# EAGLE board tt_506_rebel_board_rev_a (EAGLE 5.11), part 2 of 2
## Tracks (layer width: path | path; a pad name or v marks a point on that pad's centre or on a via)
+3.3V  (via drill 0.38 pad 0.64)
  Top 0.305: 105.09,55.88 104.46,55.88 98.11,49.53 v97.47,49.53 | v97.16,38.73 97.16,21.91 96.52,21.27 67.63,21.27 65.72,19.37 59.69,19.37 59.37,19.37 58.74,19.37 55.56,16.19 55.56,15.56 52.7,12.7 v51.44,12.7 | 78.42,67.7 78.42,66.99 78.11,66.67 75.88,66.67 75.75,66.54 U$1.5 73.21,66.54 73.03,66.36 73.03,66.04 73.17,65.89 U$1.4 | 78.42,67.7 C3.1 | 73.03,88.9 R76.1 62.13,90.7 62.23,90.81 C55.1 R77.1 | R44.1 72.92,89 73.03,88.9 | 78.42,67.7 79.13,67.7 79.38,67.94 79.38,68.9 79.69,69.22 80.11,69.22 C23.2 80.33,77.88 | v82.23,88.9 73.03,88.9 | v82.23,83.5 v82.23,86.36 | 82.23,77.88 v82.23,79.38 | v41.91,12.7 26.61,12.7 R37.1 24.83,11.93 R9.1 | 78.11,77.88 C139.+
  Top 0.406: QG1.4 75.61,77.99 C119.1 78.11,77.88 80.33,77.88 82.23,77.88 99.29,77.88 102.87,74.3 102.87,67.94 105.09,65.72 105.09,55.88 105.09,55.77 JS2.2
  Bottom 0.305: v41.91,12.7 v51.44,12.7 | v82.23,86.36 v82.23,88.9 | v82.23,79.38 v82.23,83.5 | v97.47,49.53 97.47,39.05 v97.16,38.73
  Bottom 0.406: JS2.2 108.15,55.77 109.86,57.15 R94.3
+5.0V
  Top 0.305: JS2.3 104.34,53.23 97.47,46.35 83.82,46.35 83.5,46.04 83.5,44.52 R30.2 83.31,41.59 R28.2
+8.0V  (via drill 0.38 pad 0.64, 0.38 pad 0.81)
  Top 0.305: 127.39,61.13 127.48,61.21 137.64,61.21 | 127.39,54.36 127.39,61.63 127.48,61.72 137.89,61.72 137.89,60.71 127.73,60.71 127.73,60.2 137.89,60.2 137.89,59.69 127.73,59.69 127.73,59.18 137.89,59.18 137.89,58.67 127.73,58.67 127.73,58.42 137.89,58.42 137.89,58.17 127.73,58.17 127.73,57.66 137.89,57.66 137.89,57.4 127.48,57.4 127.48,56.9 | v111.76,64.14 111.73,64.14 | R67.2 100.97,66.99 v103.82,64.14 103.82,57.47 97.16,50.8 v95.57,50.8 | v94.61,33.02 94.61,37.78 v95.57,38.73 | v87.95,33.02 72.39,33.02 70.17,30.8 70.17,28.57 v65.09,23.5 | v117.47,60.83 v117.47,50.48 | v115.89,47.62 115.89,42.86 116.2,42.55 115.99,42.55 R100.1 | v55.24,23.5 53.98,23.5 52.7,24.77 52.7,25.4 52.39,25.72 49.53,25.72 48.9,25.08 R75.1
  Top 0.406: 127.48,61.47 137.64,61.47 137.64,61.21 137.64,60.96 127.98,60.96 127.98,60.45 137.64,60.45 137.64,59.94 127.98,59.94 127.98,59.44 137.64,59.44 137.64,58.93 127.98,58.93 127.98,57.91 137.64,57.91 137.64,57.15 127.98,57.15 127.98,56.13 137.64,56.13 137.64,55.63 124.17,55.63 124.17,54.89 C114.1 124.24,56.83 124.17,56.9
  Top 0.61: 127.39,54.36 R38.1 | R60.2 111.88,67.16 112.24,66.8 112.72,66.8 Q7.2
  Top 0.813: v119.6,60.71 124.17,56.9 127.48,56.9 131.79,56.9 132.05,57.15 U1.4 | R60.2 111.09,67.09 111.09,65.6 111.73,64.96 111.73,64.14 v111.73,60.83
  Bottom 0.305: v103.82,64.14 v111.76,64.14 | v55.24,23.5 v65.09,23.5 | v95.57,38.73 v95.57,50.8 | v87.95,33.02 v94.61,33.02 | v117.47,50.48 v115.89,47.62
  Bottom 0.813: v111.73,60.83 v117.47,60.83 119.47,60.83 v119.6,60.71
  pour Top: 142.78,54.61 119.35,54.61 119.35,75.82 142.78,75.82
+12V  (via drill 0.38 pad 0.61, 0.38 pad 0.64, 0.7 pad 1.02, 0.8 pad 1.02)
  Top 0.305: v28.8,38.99 28.8,40.71 L2.2 | 28.86,28.45 v28.8,28.51 | 123.83,49.12 123.19,48.9 123.38,49.09 123.51,49.09 123.79,48.8 | 89.64,39.9 v89.22,40.01 89.32,39.9 R47.2
  Top 0.406: J3.3 105.96,66.45 104.14,68.26 104.14,74.93 97.79,81.28 67.63,81.28 62.87,76.52 62.87,75.25 59.37,71.75 57.61,71.75 R32.1 | R56.1 139.07,26.99 v140.02,27.94
  Top 0.61: 28.86,28.45 28.77,28.45 26.99,26.67 26.99,16.83 26.83,16.67 | R59.2 131.09,49.37 131.03,49.31
  Top 0.813: J3.2 107.6,68.97 107.6,68.77 107.59,68.76 J3.3 107.59,63.39 109.22,61.75 109.22,51.44 109.54,51.12 109.54,48.9 | C117.1 136.79,50.74 136.84,50.8
  Top 1.016: v89.22,40.01 89.22,32.07 88.58,31.43 73.66,31.43 72.07,29.84 72.07,27.62 v67.94,23.5 | 107.47,45.72 JS2.6 | 107.47,45.72 109.54,45.72 109.54,48.9 109.73,49.09 123.51,49.09 130.81,49.09 131.03,49.31 132.84,51.12 134.31,51.12 U1.3 135.28,51.09 135.57,50.8 136.84,50.8 | 136.84,50.8 141.29,50.8 142.24,49.85 v142.24,27.94 142.24,21.27 U$174.P$1 137.79,16.83 C147.+ | v50.8,18.1 38.1,18.1 36.51,16.51 26.99,16.51 26.83,16.67 24.77,18.73 X3.1 | 136.84,50.8 136.84,52.62 C141.+ | v89.22,45.09 104.78,45.09 105.41,45.72 107.47,45.72
  Bottom 0.305: v142.24,27.94 v140.02,27.94
  Bottom 0.381: v28.8,28.51 v28.8,38.99
  Bottom 1.016: v50.8,18.1 53.66,18.1 55.88,20.32 64.77,20.32 v67.94,23.5 | v89.22,40.01 v89.22,45.09
BAND_DETECT  (via drill 0.38 pad 0.64)
  Top 0.305: JS5.16 61.84,69.14 66.67,73.98 66.67,77.47 68.26,79.06 v68.26,79.38 | v68.26,83.5 68.26,85.09 v69.53,86.36 | v69.53,90.17 69.85,90.49 R44.2 71.12,90.59 71.12,92.71 69.85,93.98 X4.1
  Bottom 0.305: v68.26,79.38 v68.26,83.5 | v69.53,86.36 v69.53,90.17
BAND_END_FLASH_LED
  Top 0.406: JS7.10 102.55,30.37 R85.2
BATTERY
  Top 0.305: JS7.5 107.63,35.5 107.63,36.2 107,36.83 98.74,36.83 | 98.74,36.51 R47.1 98.74,38.42
  Top 0.406: 98.74,36.51 R80.1 98.74,36.83
CODE_READ  (via drill 0.38 pad 0.64)
  Top 0.305: v108.58,43.18 U$184.P$1 C99.1
  Bottom 0.305: JS7.2 105.03,42.49 105.73,43.18 v108.58,43.18
CW_SPEED  (via drill 0.38 pad 0.64)
  Top 0.305: JS7.4 105.03,38.68 105.73,39.37 111.12,39.37 111.76,40.01 v111.76,41.91 | v111.76,44.45 v111.76,46.99 | v111.76,51.44 111.76,53.34 R94.2
  Bottom 0.305: v111.76,41.91 v111.76,44.45 | v111.76,46.99 v111.76,51.44
ENC_A  (via drill 0.38 pad 0.64)
  Top 0.305: v67.94,46.99 68.58,46.35 75.25,46.35 76.8,44.81 C50.1 76.83,44.26 R35.1
  Bottom 0.305: JS6.15 59.28,46.58 59.69,46.99 v67.94,46.99
ENC_B  (via drill 0.38 pad 0.64)
  Top 0.305: 78.17,41.66 R34.1 78.18,41.59 | v67.63,41.59 78.18,41.59 | 78.18,41.59 78.18,40.15 C49.1
  Bottom 0.305: JS6.13 59.28,42.29 59.91,41.66 67.56,41.66 v67.63,41.59
FSYNC  (via drill 0.38 pad 0.64)
  Top 0.305: U$1.15 67.29,67.19 66.96,66.86 v66.96,53.53
  Bottom 0.305: v66.96,53.53 60.62,53.53 JS5.3
GND  (via drill 0.38 pad 0.61, 0.38 pad 0.64, 3.2 pad 6.45)  (2 unrouted)
  Top 0.305: R8.1 17.79,37.05 v17.49,37.08 | Q6.3 20.69,42.56 v20.8,42.67 | R6.1 26.21,38.94 v26.38,39.12 | C12.2 27.35,38.05 v27.4,38.67 | C2.2 v21.3,29.72 | R13.1 26.16,35.28 v26.13,35.31 | U$1.12 69.21,69.11 v69.5,68.77 | U$1.7 72.7,67.84 v72.68,67.82 | U$1.18 69.46,65.24 v69.5,65.6 | v103.82,15.24 103.8,15.26 | U$34.2 v99.69,65.72 | U$57.2 v95.88,65.72 v95.89,65.72 | v96.84,70.17 R68.1 | R1.1 46.89,13.23 46.99,13.34 | 46.99,13.34 R2.1 | 46.99,14.92 R36.1 | 46.99,13.34 46.99,14.92 | R54.1 R53.1 | R54.1 96.94,14.19 96.84,14.29 97.05,14.29 R54.1 | R55.1 R54.1 | R55.1 95.03,14.19 94.93,14.29 95.15,14.29 R55.1 | R55.1 93.77,14.19 v93.66,14.29 | v76.83,70.8 76.8,70.77 | C3.2 78.42,69.53 | C36.2 v80.64,65.09 | C55.2 v65.09,90.81 | R78.1 24.34,35.46 v24.77,35.88 | R14.1 27.09,35.77 v26.35,36.2 | R81.2 v98.74,30.48 | R82.1 v100.33,27.94 | R3.2 v80.64,63.18 | 11.82,53.26 v11.75,53.34 | C13.2 19.17,46.23 v19.37,46.04 | R52.1 71.86,72.45 v71.41,72.9 | U$199.2 65.87,84.94 v66.04,84.77 | R63.2 62.21,86.7 v62.23,86.68 | R4.1 68.29,59.4 v68.26,59.37 | C4.2 70.01,59.53 v69.85,59.37 | C5.2 71.85,59.47 v71.75,59.37 | C17.2 73.75,59.47 v73.66,59.37 | R5.1 75.66,59.47 v75.56,59.05 | C18.2 77.22,58.48 v77.15,58.42 | C7.2 77.22,56.9 v77.15,56.83 | C10.2 89.66,65.28 v89.53,65.41 | C16.2 87.82,65.22 v87.63,65.41 | C8.2 85.12,65.37 v85.09,65.41 | C9.2 82.45,65.31 v82.55,65.41 | R23.2 26.23,3.94 v26.35,3.49 | U$204.2 107.8,22.71 v107.95,22.86 | v22.54,6.99 C130.2 | v119.06,20.64 119.11,20.59 | C49.2 75.03,40.1 v74.93,40.01 | C50.2 75.1,44.3 v73.66,44.13 | C131.2 v23.18,12.7 | R91.1 127.85,29.43 v127.95,29.53 | R74.2 123.41,29.95 v123.19,30.16 | R96.2 117.58,31.65 v117.47,31.75
  Top 0.305: R97.2 v117.47,33.34 | C93.- v117.47,38.73 | v115.89,32.07 R65.2 | 43.5,69.26 C74.2 | U$41.3 47.31,65.31 47.31,66.67 47.94,67.31 v48.26,67.31 | R29.1 54.29,65.14 | C75.2 47.99,63.18 | U$91.2 48.37,61.28 | L13.2 45.4,57.54 | C87.2 36.65,38.1 | 34.92,33.37 U$40.3 | C90.2 30.8,32.75 | C91.2 31.75,22.33 v31.75,23.5 | C78.2 39.37,25.08 v39.37,23.5 | 39.28,31.43 C137.- | C66.2 | D19.A 53.17,47.8 v53.02,47.94 53.17,48.09 D10.A | C82.2 46.78,47.1 v46.67,46.99 | C81.2 46.6,48.83 v46.67,48.9 | D11.A 39.86,48.09 v40.01,47.94 39.86,47.8 D18.A | C83.2 56.76,28.82 v56.83,28.89 | v32.7,37.15 C135.- | L16.2 52.31,30.08 v52.39,30.16 | D9.A 56.03,26.52 v56.2,26.35 56.03,26.18 D20.A | 46.99,14.92 47.94,14.92 v48.26,15.24
  Top 0.406: QG1.2 67.92,72.89 v67.91,72.9 | QG1.2 71.4,72.89 v71.41,72.9 | QG1.2 v69.51,74.48 v69.5,74.49 | 75.72,74.93 v75.85,74.8 | 124.17,53.06 124.01,52.9 122.84,52.9 122.21,52.26 121.38,52.26 | 103.8,15.26 R17.2 | C63.2 28.55,72.68 v29.21,72.71 | C62.2 28.41,71.28 v29.21,71.44 | C67.2 28.54,69.89 v29.21,69.85 | v26.04,55.56 25.87,55.73 | v27.3,55.56 27.27,55.6 | v28.57,55.56 28.66,55.79 | R10.1 33.11,53.25 v32.7,53.34 | 9.89,61.55 v9.84,61.59 | 120.33,5.97 U$176.2 | C132.2 12.8,15.77 v12.7,15.88 | C150.- v25.08,25.4 | 1.54,61.55 v1.59,61.59 | C136.- 137.07,28.49 v137.16,28.57 | C107.2 132.53,26.8 v132.4,26.67 | C51.2 67.63,74.81 v67.63,73.66
  Top 0.61: JS2.5 JS2.4 | C111.2 v116.81,76.2 | v121.38,50.55 121.38,52.26 | v124.17,51.88 124.17,53.06 C114.2 | C110.2 113.82,65.47 v113.76,65.53 | C119.2 75.72,74.93 | C65.2 39.76,76.27 v39.69,76.2 | C64.2 39.82,74.43 v39.69,74.3 | 25.87,55.73 C71.2 | 27.27,55.6 C72.2 | 28.66,55.79 C70.2 | R39.2 v125.74,52.38 v125.73,52.39 | 76.8,70.77 C1.2 | 78.42,69.53 v78.42,70.8 | v24.13,94.61 D12.A | C129.2 16.51,46.51 v15.97,45.97 | 11.82,53.26 C6.2 | C44.2 v15.56,78.11 | C37.2 v15.56,80.33 | C42.2 v14.61,62.87 | C123.2 v16.83,62.87 | C133.2 v15.88,64.45 | C33.2 v1.27,72.07 C34.2 | C48.2 v4.76,74.3 | C45.2 9.89,61.55 | v120.33,4.45 120.33,5.97 | v118.43,4.76 C120.2 | C149.- v31.43,53.66 | v113.67,61.91 113.67,63.5 | C142.- v113.98,77.79 | v78.11,73.03 C139.- | 119.11,20.59 C94.2 | LM358.4 124.61,21.12 v124.46,20.95 | C152.- v117.47,22.54 | C54.2 21.73,76.69 v21.59,76.83 | D5.C v18.41,80.64 | C43.2 1.54,61.55 | C29.2 v6.67,68.9 | 21.27,65.09 C39.2 | 21.27,65.09 v22.54,65.09 | v22.54,62.55 C122.2 21,64.82 21.27,65.09 | C25.- 28.8,50.4 v28.89,50.48 | C146.- 138.98,22.45 v138.11,21.59 | R45.2 119.18,19.16 v119.06,19.05 | C117.2 139.51,49.4 v139.7,49.21 | C100.2 v140.65,46.98 v140.65,46.99 | C109.2 139.63,47.06 v139.7,46.99 | LM386M-1.4 136.58,45.35 v136.53,45.4 | LM386M-1.2 136.58,42.81 v136.53,42.86 | C102.- 129.63,36.6 v129.54,36.51 | R51.1 133.76,47.4 v133.99,47.62 | C126.- v124.78,41.91 | v29.84,91.12 C128.2 | C56.2 30.8,85.22 v30.8,86.68 | v28.89,86.68 28.89,85.22 C57.2 28.94,85.09 27.03,85.09 | C58.2 27.03,85.09 | 27.03,85.09 v25.72,85.09 | C138.- 53.74,68.58 v55.24,68.58 | v43.5,67.94 43.5,69.26 | 54.29,65.14 v54.29,63.82 | 47.99,63.18 v49.21,63.18 | 48.37,61.28 v49.85,61.28
  Top 0.61: 45.4,57.54 v45.4,59.05 | 36.65,38.1 v38.1,38.1 | v34.92,31.43 34.92,33.37 | C125.2 v32.07,33.97 | 30.8,32.75 v30.8,33.97 | v31.11,24.45 C21.2 | v37.47,31.43 39.28,31.43 | v37.15,81.28 C66.2 | L1.1 49.44,24.22 v49.21,24.13 | R84.1 v116.84,20.64 | C151.- v119.38,12.7 | D6.A 121.5,9.63 v121.6,9.53
  Top 0.813: J4.2 142.78,84.23 v142.88,84.14
  Top 1.016: C141.- v141.6,52.7 | v137.79,9.53 C147.-
  Bottom 0.305: JS2.4 107.58,50.67 | v26.38,39.12 26.64,39.12 v27.4,38.67 | v78.42,70.8 v76.83,70.8 | MNT6.MNT 140.57,91.58 J1.1 130.67,91.44 120.97,91.44 119.7,92.71 | MNT7.MNT 140.97,6.57 140.97,6.67 134.46,10.32 U$162.5 U$162.4 124.83,13.63 U$162.1 | 93.66,13.97 v93.66,14.29 89.53,10.16 MNT2.MNT | 93.77,14.19 93.98,14.4 | 111.44,92.71 109.54,90.81 109.54,84.77 112.39,81.92 112.39,79.38 v113.98,77.79
  other vias: 11.4,27.81 11.58,32.51 3.52,21.34 7.08,45.97 5.3,38.1 5.3,36.07 3.52,37.08 5.05,45.97 5.3,34.04 5.3,32 5.3,29.97 5.3,27.94 7.33,27.94 9.37,27.94 3.52,35.05 3.52,33.02 3.52,30.99 3.52,28.96 3.52,26.92 15.53,27.75 13.43,27.75 5.56,21.34 7.59,21.34 9.62,21.34 11.65,21.34 13.43,21.34 13.43,23.37 3.52,23.37 3.52,25.15 15.34,21.34 17.24,21.34 19.15,21.34 21.05,21.34 22.96,21.34 24.86,21.34 24.86,23.24 22.96,23.24 21.05,23.24 19.15,23.24 17.24,23.24 15.34,23.24 5.49,23.24 7.72,23.24 9.62,23.24 11.53,23.24 15.53,25.53 13.3,25.53 11.4,25.53 9.18,25.53 7.27,25.53 5.37,25.53 7.27,33.78 7.27,31.88 7.27,29.97 7.27,35.69 15.84,29.97 15.84,31.88 15.84,33.78 15.84,35.69 15.84,37.59 15.84,39.81 7.27,37.59 7.27,39.81 9.18,36.96 13.94,36.96 11.4,36.96 9.49,39.81 13.62,39.81 15.84,42.04 7.27,42.04 7.27,43.94 15.84,43.94 9.49,42.04 13.94,42.04 13.94,43.94 9.49,43.94 11.72,42.99 11.72,40.77 5.08,43.81 5.08,42.23
  pour Top: 16.73,46.67 3.78,46.67 3.78,38.35 2.51,38.35 2.51,20.32 25.94,20.32 25.94,23.94 16.61,23.94 16.61,28.7
  pour Bottom: 0.22,95.5 0.29,0.38 59.05,0.32 59.05,18.1 85.72,18.1 85.72,0.32 87.95,0.32 98.04,0.38 144.56,0.38 144.49,95.5
MEDIUM_A8  (via drill 0.38 pad 0.64)
  Top 0.305: R71.1 97.79,63.18 98.42,62.55 101.92,62.55 102.55,61.91 v102.55,57.78
  Bottom 0.305: v102.55,57.78 102.55,35.88 102.87,35.56 104.92,35.56 JS7.6
MP_A  (via drill 0.38 pad 0.64)
  Top 0.305: v90.49,24.13 v90.49,38.73 | v90.49,17.46 90.49,16.83 91.76,15.56 100.01,15.56 100.65,14.92 100.65,10.79 U$168.P$2 | v67.94,55.56 72.39,55.56 74.3,53.66 89.53,53.66 90.49,52.7 v90.49,49.85
  Bottom 0.305: JS5.8 63.04,57.29 64.77,55.56 v67.94,55.56 | v90.49,38.73 v90.49,49.85 | v90.49,17.46 v90.49,24.13
MP_B  (via drill 0.38 pad 0.64)
  Top 0.305: v92.08,24.13 v92.08,38.73 | v92.08,17.46 92.08,17.14 92.71,16.51 100.33,16.51 101.6,15.24 101.6,7.62 100.97,6.99 U$168.P$4 | v69.22,56.52 72.71,56.52 74.61,54.61 90.81,54.61 92.08,53.34 v92.08,49.85
  Bottom 0.305: JS5.12 63.36,62.37 63.82,61.91 63.82,57.78 65.09,56.52 v69.22,56.52 | v92.08,38.73 v92.08,49.85 | v92.08,17.46 v92.08,24.13
MP_C  (via drill 0.38 pad 0.64)
  Top 0.305: v93.66,24.13 v93.66,38.73 | v93.66,17.46 100.65,17.46 102.55,15.56 102.55,5.4 101.6,4.45 U$168.P$6 | v67.94,57.47 73.03,57.47 74.93,55.56 92.08,55.56 93.66,53.98 v93.66,50.8
  Bottom 0.305: JS5.14 63.36,64.91 64.77,63.5 64.77,58.1 65.41,57.47 v67.94,57.47 | v93.66,38.73 v93.66,50.8 | v93.66,17.46 v93.66,24.13
N$1
  Top 0.61: 16.83,86.36 16.83,83.6 X1.1 19.75,83.44 21.27,81.92 21.27,80.2 L4.2 | 16.83,86.36 8.26,86.36 7.94,86.68 6.15,86.68 X11.2 | 16.83,86.36 23.18,86.36 24.45,87.63 C127.1
N$2  (via drill 0.38 pad 0.64)
  Top 0.305: JS5.1 60.69,51.05 63.12,51.05 v63.18,51.12 | U$1.14 68.19,67.82 66.83,67.82 66.01,66.99 66.01,53.02 66.99,52.04 v66.99,51.12
  Bottom 0.305: v63.18,51.12 v66.99,51.12
N$3
  Top 0.305: JS5.5 59.37,54.82 59.37,55.88 59.63,56.13 63.98,56.13 65.25,57.4 65.25,67.31 66.43,68.49 U$1.13
N$4
  Top 0.305: U$1.11 68.17,69.72 66.58,69.72 64.48,67.63 64.48,59.69 63.47,58.67 59.63,58.67 59.37,58.42 59.37,57.36 JS5.7
N$5
  Top 0.305: JS5.9 59.3,60.89 59.37,60.96 63.18,60.96 63.82,61.59 63.82,67.94 66.36,70.48 69.22,70.48 70.58,69.11 U$1.9
N$6
  Top 0.305: U$1.1 75.71,63.97 76.83,65.09 C36.1 R3.1
N$7
  Top 0.305: L15.2 80.39,58.68 C18.1 C7.1 82.2,56.9 L18.1
N$8
  Top 0.305: U$1.19 70.96,64.61 71.75,63.82 71.75,62.48 C5.1 73.63,62.38 C17.1 73.68,62.26 73.66,62.23 75.56,62.23 | 75.56,62.23 75.62,62.23 R5.2 75.6,62.19 75.56,62.23 | 75.56,62.23 75.56,61.91 77.15,61.91 77.47,61.59 77.47,60.61 L15.1
N$9
  Top 0.305: U$1.20 68.22,62.52 R4.2 C4.1
N$10
  Top 0.305: U$1.6 75.13,67.19 75.56,67.63 76.7,67.63 C1.1
N$11
  Top 0.305: L18.2 82.55,62.17 | 82.55,62.17 C9.1 | 82.55,62.17 82.64,62.27 C8.1 85.12,60.07 L17.1
N$12
  Top 0.305: U$160.3 25.28,30.23 24.61,30.23 23.82,31.01 R12.1 18.3,31.01 L14.2 18.26,32.91 U$159.3 18.62,35.56 C20.1
N$13  (via drill 0.38 pad 0.64)
  Top 0.305: v86.04,56.52 87.95,58.42 87.95,59.85 L17.2 C16.1 C10.1 | C11.2 46.67,51.36 47.62,50.48 v53.98,50.48 | v58.1,44.13 56.2,46.04 v56.2,46.99
  Top 0.406: v86.04,50.8 68.9,50.8 66.67,48.58 66.67,47.31 | 66.67,47.31 | 66.67,47.31 | v66.67,44.13 66.67,47.31
  Bottom 0.305: v58.1,44.13 v66.67,44.13 | v53.98,50.48 54.29,50.16 54.29,47.62 54.93,46.99 v56.2,46.99
  Bottom 0.406: v86.04,50.8 v86.04,56.52
N$14
  Top 0.305: 20.49,36.83 20.49,35.74 C20.2 | 20.49,36.83 R8.2 | 20.49,36.83 20.32,37 20.32,37.78 20,38.1 U$158.1 19.86,39.05 18.1,39.05 R86.1
N$15
  Top 0.305: U$159.2 22.61,34.22 22.86,33.97 R78.2
N$16
  Top 0.305: 24.4,32.36 U$160.2 24.33,32.43 | U$159.1 24.22,32.32 24.33,32.43 | 24.33,32.43 24.33,34.04 R13.2
N$17  (via drill 0.38 pad 0.64)
  Top 0.305: 27.62,32.34 U$160.1 | R40.1 27.62,32.34 | 27.62,32.34 27.62,33.97 27.94,33.97 R14.2 28.65,34.08 29.18,34.61 29.18,37.75 30.16,38.73 30.16,41.27 U$185.P$1 33.02,44.13 37.47,44.13 38.42,45.09 38.42,53.66 39.05,54.29 42.86,54.29 43.81,55.24 43.81,55.88 | C118.1 43.5,63.89 43.5,63.18 43.81,62.87 v43.81,60.64 | 43.81,55.88 v43.81,58.1 | C11.1 44.9,55.75 44.77,55.88 43.81,55.88
  Bottom 0.305: v43.81,58.1 v43.81,60.64
N$18
  Top 0.305: 23.33,39.03 R6.2 23.39,38.91 U$158.2 21.91,38.1 22.17,37.84 R22.2
N$19
  Top 0.305: R22.1 25.46,37.33 C12.1
N$20  (1 unrouted)
  Top 0.305: R15.1 20.16,27.91 C2.1
  Top 0.406: L14.1 18.41,28.26 18.41,27.94 18.44,27.91 18.44,26.33 19.05,25.4 20.39,25.4 20.16,26.12 20.16,27.91
N$21
  Top 0.305: U$158.3 21.1,41.1 21.91,41.91 21.91,43.18 | 21.91,43.18 21.59,43.18 20.4,44.37 Q6.1 | 21.91,43.18 23.62,43.18 C15.2 25.18,43.1 D1.C
N$22
  Top 0.381: D1.A D2.C
N$23
  Top 0.305: U$131.1 23.43,48.96 23.81,48.58 23.81,46.67 24.13,46.35 25.19,46.35 R20.1 25.21,44.96 25.4,44.77 25.72,44.77 25.72,45.09 25.46,45.09 D2.A
  Top 0.381: 23.78,44.89 C15.1 25.18,44.8 D2.A
N$24
  Top 0.305: 25.11,49.53 25.4,49.53 25.21,49.34 R20.2 25.3,47.94 26.04,47.94 26.35,47.62 27.07,47.62 C25.+ | 25.11,49.53 25.08,49.53 | 25.11,49.53 R33.1
N$25  (via drill 0.38 pad 0.64)
  Top 0.305: R50.2 140.59,38.48 140.97,38.1 140.97,22.54 135.25,16.83 v132.72,16.83 | C32.2 v129.54,16.83
  Bottom 0.305: v129.54,16.83 v132.72,16.83
N$26  (via drill 0.38 pad 0.61)
  Top 0.305: v22.19,44.32 22.19,46.32 22.54,46.67 22.54,47.38 U$131.3 22.19,47.16 C13.1
  Top 0.381: v23.46,40.83 L2.1
  Bottom 0.305: v22.19,44.32 22.19,44.16 22.54,43.81 22.54,41.75 v23.46,40.83
N$27
  Top 0.305: Q6.2 18.16,44.42 | U$131.2 21.42,49.54 C19.1 19.68,49.21 19.68,48.58 19.37,48.26 18.1,48.26 17.78,47.94 17.78,46.04 18.5,45.32 Q6.2 | R86.2 18.1,43.18 18.41,43.5 18.41,44.68 Q6.2
N$28
  Top 0.61: U$37.CLS 6.94,53.02 C46.1
N$29  (via drill 0.38 pad 0.64)
  Top 0.305: v70.8,23.18 78.42,23.18 79.69,24.45 v79.69,28.26 | v79.69,42.86 79.69,44.13 | 79.69,44.13 79.75,44.13 R35.2 | R30.1 79.88,44.32 79.69,44.13
  Bottom 0.305: X2.1 69.82,22.19 v70.8,23.18 | v79.69,28.26 v79.69,42.86
N$30
  Top 0.305: R21.2 33.04,51.75 33.02,51.75 32.7,52.07 27.3,52.07 26.99,52.39 26.99,53.66 C149.+ 18.41,53.66 18.38,53.62 18.1,53.34 17.78,53.02 16.59,53.02 R19.1 14.93,53.15 C6.1
N$31
  Top 0.305: RD16HHF1.1 14.18,49.95 | R19.2 16.51,51.4 C129.1 16.93,50.06 17.46,49.53 C19.2
  Top 0.406: C129.1 14.17,50.06 RD16HHF1.1
N$32
  Top 0.305: R21.3 37.15,46.62 37.15,53.98 37.7,54.53 R18.2
N$33
  Top 0.305: R10.2 35.88,53.23
  Top 0.406: R21.1 31.89,45.86 35.88,49.85 35.86,49.87 R10.2
N$34
  Top 0.406: R81.1 R80.2
N$35
  Top 0.61: U$37.GRS U$37.CLF
N$36
  Top 0.61: X6.2 6.17,57.02 8.89,54.29 8.89,53.7 C46.2
N$37
  Top 0.406: C45.1 6.54,61.35 TOROID2.P$1 4.89,61.35 C43.1 3.63,59.92 X6.1
  Top 0.61: C30.1 C24.1 1.86,65.22 TOROID2.P$1
N$38
  Top 0.406: C24.2 C30.2 | C30.2 3.86,70.44 3.81,70.48 3.81,70.22 C30.2 | C30.2 4.13,70.17 4.76,70.8 4.76,72.03 C34.1
  Top 0.61: C121.1 C47.1 7.26,80.64 TOROID1.P$1 9.53,78.38 6.67,75.52 C29.1 4.81,72.44 C34.1 | C24.2 5.4,67.94 5.71,67.63 TOROID2.P$2
N$39
  Top 0.61: C48.1 3.44,75.93 3.49,75.88 3.17,75.88 C48.1 | X11.1 1.66,85.17 1.27,84.77 1.27,82.82 | 1.27,82.82 C121.2 | 1.27,80.69 1.27,82.82 | 1.27,80.69 C47.2 | 1.27,78.42 1.27,80.69 | 1.27,78.42 4.25,78.42 TOROID1.P$2 | 1.27,78.42 C33.1 C48.1
N$40
  Top 0.61: TOROID4.P$1 17.66,55.2 C41.1 C124.1 12.11,55.2 11.75,55.56 11.75,57.47 | C123.1 C42.1 14.52,59.24 L3.1 12.25,59.24 12.25,58.1 11.75,57.47 | X6.3 8.88,57.47 11.75,57.47
N$41
  Top 0.61: C124.2 C41.2 16.88,57.2 17.14,57.47 18.73,57.47 | 13.09,66.99 TOROID3.P$1 | 13.09,66.99 13.09,68.97 14.92,70.8 14.92,73.98 14.61,74.3 C40.1 C38.1 | 18.73,57.47 21.48,57.47 TOROID4.P$2 | 18.73,57.47 19,57.74 C122.1 C39.1 19,66.09 18.1,66.99 13.09,66.99
N$42
  Top 0.61: X11.3 7.58,84.77 11.43,84.77 12.06,84.14 12.06,80.33 C37.1 | C37.1 12.06,80.38 | C37.1 C44.1 12.02,77.83 12.06,77.79 11.75,77.79 11.75,76.25 C38.2 C40.2 11.7,72.44 12.06,72.07 12.91,72.07 TOROID3.P$2
N$43
  Top 0.406: R38.2 127.44,52.7 R39.1 127.46,51.09 U1.1
N$44
  Top 0.305: D4.C 118.01,35.14 R65.1 115.89,36.73 R64.2
N$45  (via drill 0.38 pad 0.64)
  Top 0.305: JS6.11 59.28,39.94 59.98,39.24 60.29,39.24 60.61,38.92 60.61,34.48 60.93,34.16 63.31,34.16 v63.5,33.97 | U$148.1 107.32,15.04 R17.1 107,15.36 107,18.41 106.36,19.05 v85.72,19.05 | v70.17,33.97 v85.72,33.97
  Bottom 0.305: v63.5,33.97 v70.17,33.97 | v85.72,33.97 v85.72,19.05
N$46
  Top 0.305: R9.2 22.56,10.04 C130.1 19.15,10.06 U$163.3 | U$163.3
N$47
  Top 0.305: U$197.3 132.72,33.66 132.4,33.97 131.66,33.97 R66.1 129.01,34.19 127.64,35.56 124.78,35.56 123.51,36.83 118.75,36.83 | R100.2 118.01,40.74 118.75,40.01 118.75,38.97 C93.+ 118.97,37.06 118.75,36.83 | 117.47,36.83 R64.1 118.75,36.83
N$48
  Top 0.305: R61.1 63.52,87.12 U$199.3
N$49
  Top 0.305: LM386M-1.3 138.58,43.96 C100.1 140.65,41.34 R50.1
N$50
  Top 0.305: R73.2 126.15,31.85 126.05,31.75 | 126.05,31.75 U$190.1 | 126.05,31.75 124.56,31.75 R74.1 C35.2
N$51
  Top 0.61: 24.13,77.79 24.13,79.88 L4.1 | X12.2 24.22,77.7 24.13,77.79 | C31.1 24.13,77.79
N$52
  Top 0.406: 18.41,73.98 18.73,74.3 | 18.41,73.98 18.41,73.66 | D5.A 18.41,73.98 | D5.A 18.41,74.3 | D5.A 21.61,74 C54.1 21.91,73.88 | 21.91,73.88 24.08,73.88 C31.2 | L20.2 21.74,73.71 21.91,73.88
N$53
  Top 0.406: L20.1 24.06,68.04 R41.2
N$54
  Top 0.305: U$166.P$1 45.4,11.11 45.09,11.43 45.09,11.64 R1.2
N$55
  Top 0.406: C64.1 43.18,74.38 43.18,73.03 42.23,72.07 42.23,62.23 42.37,62.08 X13.3 | C66.1 40.32,81.23 40.32,80.33 40.91,79.74 C61.2 42.23,79.69 42.23,77.79 43.18,76.83 43.18,76.2 43.5,75.88 42.86,75.88 42.86,76.2 42.93,76.27 C65.1
  Top 0.61: C64.1 C65.1
N$56
  Top 0.61: C59.1 35.15,83.43 C56.1 30.82,83.5 28.89,83.5 28.96,83.43 C57.1 C58.1 27.08,80.3 X12.3
N$57
  Top 0.61: U$69.1 41.03,86.44 39.37,84.77 39.37,83.46 L21.1 39.23,83.5 36.83,83.5 36.87,83.46 C59.2
N$58
  Top 0.61: C61.1 42.14,81.48 | C61.1 43.02,81.44 44.03,82.46 U$70.1 | L21.2 42.23,83.31 42.23,81.28 42.17,81.34 C61.1
N$59
  Top 0.406: C68.1 C67.1 C62.1 C63.1 26.16,74.18 X12.1
N$60
  Top 0.406: 26.76,66.36 26.67,66.36 | 26.76,66.36 27.62,66.36 27.86,66.59 C68.2 29.12,68.49 31.55,70.92 U$80.1 | L23.1 26.76,66.36
N$61
  Top 0.305: U$81.1 31.26,66.99 30.16,66.99 26.84,63.67 L23.2 26.64,62.11 C69.1
N$62
  Top 0.305: C69.2 26.77,58.96 C72.1 C71.1 | C71.1 25.76,58.78 25.72,58.74 | C70.1 C71.1
  Top 0.406: C70.1 30.75,58.78 31.75,57.78 31.75,57.16 L24.1 31.56,56.09 C73.1
N$63
  Top 0.305: L24.2 34.29,57.05 34.29,57.15 41.27,57.15 41.62,56.81 X13.1
  Top 0.406: L24.2 34.36,55.48 C73.2
N$64
  Top 0.406: U$41.1 44.77,65.12 44.77,60.01 44.11,59.35 X13.2
N$65
  Top 0.305: L13.1 48.14,56 48.26,55.88 49.69,55.88 C80.2 50.47,55.73 D17.A 52.39,55.73 | 52.39,55.73 D22.A | 52.39,55.73 52.41,55.4 Q1.1
N$66
  Top 0.406: U$41.4 49.03,65.22 50.16,66.36 50.16,69.17 U$103.1
N$67
  Top 0.305: U$103.2 52.04,66.61 R99.2 54.19,66.57 54.29,66.67 54.29,66.85 R29.2
N$68  (2 unrouted)
  Top 0.305: U$41.8 44.77,70.51 44.77,70.8 | 44.77,70.8 44.77,71.75 45.4,72.39 49.53,72.39 50.48,71.44 50.8,71.44 50.84,71.39 | 51.13,71.44 53.98,71.44 | C74.1 43.66,70.8 44.77,70.8
  Top 0.406: R32.2 55.59,71.44 53.98,71.44 53.66,71.44 C138.+
N$69
  Top 0.305: U$41.2 46.09,65.17 C75.1 46.11,62.96 U$91.3
N$70
  Top 0.305: C127.2 26.89,88.9 R88.2
N$71
  Top 0.305: Q3.2 55.26,33.47 Q4.1 54.34,30.52 53.96,30.15 C83.1 53.83,28.69 D9.C 53.83,26.67 | 53.83,26.67 D20.C | R24.1 53.82,26.68 53.83,26.67
N$72  (via drill 0.38 pad 0.64)
  Top 0.305: 94.93,73.34 95.03,73.24 | 94.93,73.34 R70.2 | R67.1 R69.2 98.64,73.34 96.84,73.34 | 94.93,73.34 96.84,73.34 | 96.84,73.34 R68.2 | v95.25,80.33 67.94,80.33 63.98,76.36 63.98,75.09 v58.74,69.85 | v95.25,75.56 95.25,73.66 94.93,73.34 | 45.09,41.59 v47.31,41.59 | v55.88,67.63 55.88,61.59 55.24,60.96 55.24,58.74 55.88,58.1 55.88,55.56 | 55.88,55.56 55.88,49.53 55.24,48.9 55.24,46.35 54.81,45.92 R25.2 54.93,45.36 54.93,42.55 53.98,41.59 v50.48,41.59 | R31.1 55.74,55.7 55.88,55.56 | R26.2 45.06,41.62 45.09,41.59 | 45.09,41.59 43.18,41.59 42.55,40.96 42.55,34.61 41.59,33.66 41.59,30.48 | 41.59,30.48 42.23,29.84 42.23,29.05 R27.2 | R24.2 49.22,26.68 48.58,26.04 v44.45,26.04 | 41.59,30.48 v42.86,30.48
  Bottom 0.305: v58.74,69.85 57.15,68.58 v55.88,67.63 | v95.25,80.33 v95.25,75.56 | v47.31,41.59 v50.48,41.59 | v42.86,30.48 43.18,30.16 43.18,26.67 43.5,26.35 44.13,26.35 v44.45,26.04
N$73  (1 unrouted)
  Top 0.305: 42.06,44.2 D18.C | D11.C 42.06,51.79 Q1.2 | D18.C D11.C | D11.C 43.35,48.9 C81.1 | R26.1 42.19,46.86 D18.C
N$74
  Top 0.305: Q4.2 44.69,30.71 43.81,29.84 43.81,29.11 C79.2 D8.A D21.A 49.06,29.04 49.53,28.57 49.53,28.43 L16.1
N$75
  Top 0.305: C80.1 50.02,57.93 D17.C D22.C 53.98,57.93 | 54.63,57.15 R31.2 54.48,57.62 53.98,57.93 | C77.2 53.18,61.44 53.98,60.64 53.98,57.93
N$76
  Top 0.305: C84.2 39.8,33.86 40.64,33.02 40.64,27.62 40.96,27.3 R27.1 43.86,27.31 C79.1 45.22,27.34 D8.C D21.C
N$77
  Top 0.305: R11.2 C60.1
N$78
  Top 1.016: 2,42.73 C14.1 2.01,42.86 | 2.01,42.86 2.01,47.73 U$37.RDF | 1.27,40.23 1.27,19.37 1.91,18.73 X3.2 | 1.27,40.23 C148.+ | 1.27,40.23 1.27,42.12 2.01,42.86
N$79  (via drill 0.38 pad 0.64)
  Top 0.305: v33.02,10.48 33.02,6.99 32.58,6.54 U$61.1 26.28,6.54 R23.1 | JS6.5 58.42,32.85 57.78,32.22 57.78,24.45 52.39,19.05 37.47,19.05 36.2,17.78 v33.02,17.78
  Bottom 0.305: v33.02,10.48 v33.02,17.78
N$80
  Top 0.305: 75.49,72.31 U$186.P$1
  Top 0.406: U$1.8 75.25,68.49 75.53,68.77 75.53,72.26 75.49,72.31 74.9,72.9 QG1.3
N$81
  Top 0.305: U$40.1 37.5,35.96 L25.2 39.76,36.31 C84.1
N$82
  Top 0.305: C90.1 30.79,30.9 C125.1 | C90.1 30.87,31.11 32.07,31.11 32.38,30.8 33.66,30.8 34.29,30.16 35.56,30.16 36.2,29.53 36.2,28.23 U$40.7 36.2,28.17 36.2,27.3 36.85,26.65 C89.1 37.15,25.85 U$187.P$1 | C21.1 31.11,30.16 30.8,30.48 30.8,30.8 30.72,30.87 C90.1
N$83  (1 unrouted)
  Top 0.305: U$40.8 37.56,28.26 39.37,28.26 | C137.+ 39.45,28.26 C78.1 41.09,26.54 41.27,26.35 41.27,25.18 R75.2
N$84
  Top 0.305: U$40.6 34.96,26.34 C89.2 35.24,26.05 35.24,22.23 35.9,21.57 Q5.2
N$85
  Top 0.305: R12.2 23.49,29.31 23.84,28.96 26.13,28.96 27.65,30.48 R40.2 27.65,30.73
N$86
  Top 0.305: U$40.5 33.66,28.17 C60.2
N$87
  Top 0.305: LM358.2 124.3,23.66 123.83,24.13 C85.1 R42.1 119.81,24.55 R43.2
N$88
  Top 0.406: QG1.1 69.53,77.96 69.53,76.83 69.24,76.54 C51.1
N$89
  Top 0.406: LM358.6 132.55,22.39 133.03,21.91 134.02,21.91 R48.2 134.07,20.02 R7.2
N$90  (via drill 0.38 pad 0.64)
  Top 0.305: v53.98,22.23 53.98,21.91 51.75,19.68 34.29,19.68 33.66,20.32 R11.1 33.53,20.62 C91.1 | v63.82,22.23 v95.25,22.23 | v98.42,21.27 113.67,21.27 116.85,24.45 R43.1
  Bottom 0.305: v95.25,22.23 v98.42,21.27 | v53.98,22.23 v63.82,22.23
N$91
  Top 0.305: C99.2 113.67,38.42 114.62,37.47 114.62,26.99 115.25,26.35 122.14,26.35 122.24,26.25 | 122.24,26.25 C85.2 123.93,26.35 125.73,26.35 126.26,25.82 LM358.1 128.1,24.93 128.59,24.45 128.59,22.54 130.01,21.12 LM358.5 131.44,21.11 131.44,16.51 131.13,16.19 C92.1 | 122.24,26.25 R42.2
N$92  (via drill 0.38 pad 0.64)
  Top 0.305: LM358.3 v124.14,22.39 122.39,22.39 | 122.39,22.39 122.24,22.54 C152.+ | 122.39,22.39 122.39,20.76 C94.1 122.22,19.38 122.24,19.37 122.24,19.18 R45.1 | R46.1 126.74,26.61 v126.68,26.67
  Bottom 0.305: v126.68,26.67 125.73,26.67 124.78,25.72 124.78,23.02 v124.14,22.39
N$93  (via drill 0.38 pad 0.64)
  Top 0.305: LM358.7 129.71,23.66 v129.54,23.5 | C97.1 129.61,20.25 v129.54,20.32
  Top 0.406: LM358.7 133.97,23.66 R48.1
  Bottom 0.305: v129.54,20.32 v129.54,23.5
N$94
  Top 0.406: R7.1 135.79,22.99 C146.+
N$95
  Top 0.305: D6.C 122.02,15.02 123.19,16.19 127.64,16.19 127.95,16.51 127.95,17.48 D7.A 127.86,19.09 C97.2
N$96
  Top 0.305: U$91.1 48.38,59.37 R49.2
N$97
  Top 0.406: U$176.3 122.68,8.38 123.51,9.21 131.44,9.21 132.08,9.84 132.08,11.4 U$162.3 132.11,12.03 131.13,13.02 C92.2 131.13,13.97
N$98  (via drill 0.38 pad 0.64)
  Top 0.305: v81.92,23.18 v81.92,28.26 | X2.3 v81.92,19.05 | R34.2 81.54,41.66 R28.1 81.73,39.24 v81.92,39.05
  Bottom 0.305: v81.92,28.26 v81.92,39.05 | v81.92,19.05 v81.92,23.18
N$99  (via drill 0.38 pad 0.64)
  Top 0.305: v41.59,11.11 41.27,11.43 37.47,11.43 | U$61.2 37.39,11.35 37.47,11.43 | 37.47,11.43 31.43,11.43 31.11,11.75 27.94,11.75 26.35,10.16 26.23,10.16 R37.2 | U$148.2 112.32,6.75 108.9,10.16 108.9,18.1 107,20 77.15,20 76.52,20.64 68.26,20.64 66.36,18.73 59.05,18.73 56.2,15.88 56.2,15.24 53.34,12.38 53.34,12.06 v52.39,11.11
  Bottom 0.305: v41.59,11.11 v52.39,11.11
N$100
  Top 0.61: LM386M-1.5 130.86,45.35 130.49,45.72 129.42,45.72 C103.1 128.87,45.75 127.95,46.67 127,46.67 | 127,46.67 127.32,46.99 | 127,46.67 126.79,46.67 C105.+
N$101
  Top 0.305: LM386M-1.8 134.67,41.54 134.94,41.27 134.94,39.69 | 134.94,39.69 C22.- | 134.94,39.69 134.94,38.1 134.62,37.78 134.09,37.78 C134.2
N$102
  Top 0.305: LM386M-1.1 138.46,40.12 C22.+
N$103
  Top 0.61: LM386M-1.7 132.03,42.81 131.13,41.91 C102.+
N$104
  Top 0.61: R51.2 129.44,47.4 C103.2
N$105  (via drill 0.7 pad 1.02)
  Top 1.016: D14.C 121.94,78.08 122.56,77.47 140.97,77.47 v141.29,77.79 141.29,79.99 D15.C
  Bottom 1.016: U$173.P$1 143.8,19.34 143.8,76.23 142.24,77.79 v141.29,77.79
N$106
  Top 0.305: U$166.P$3 43.81,6.99 43.5,7.3 43.5,13.02 43.81,13.34 R2.2
N$107
  Top 0.305: LM358.8
  Top 0.406: R56.2 137.7,25.49 C136.+ 135.19,25.1 C107.1 133.66,24.93 LM358.8 130.01,24.93 129.86,25.08 129.86,26.6 R46.2
N$108
  Top 0.305: JS5.11 59.3,63.11 59.69,63.5 62.87,63.5 63.18,63.82 63.18,68.26 66.04,71.12 69.53,71.12 70.8,69.85 73.34,69.85 | U$1.10 73.43,69.77 73.34,69.85 | 73.34,69.85 73.34,70.91 R52.2
N$109
  Top 0.305: U$166.P$5 43.5,4.45 42.86,5.08 42.86,13.97 43.81,14.92 R36.2 45.4,14.92
N$110
  Top 0.305: U$168.P$1 99.06,11.75 R53.2
N$111
  Top 0.305: U$168.P$3 95.89,6.99 95.25,7.62 95.25,10.48 97.16,12.38 R54.2
N$112
  Top 0.305: U$168.P$5 95.25,4.45 94.61,5.08 94.61,11.85 R55.2
N$113
  Top 0.305: R89.1 55.88,88.9 U$143.4
N$114
  Top 0.305: X9.1 114.53,80.73 112.71,82.55 112.71,83.57 R57.2 112.73,87.22 U$188.1
N$115  (via drill 0.38 pad 0.64)
  Top 0.406: R58.1 120.64,83.5 120.56,83.59 117.16,83.59 | 117.16,83.59 R57.1 | 117.16,83.59 117.08,83.51 X9.2 118.43,78.87 118.43,51.12 v119.06,50.48 | C105.- 118.14,46.65 v118.11,46.67
  Bottom 0.406: v118.11,46.67 118.11,49.53 v119.06,50.48
N$116
  Top 0.305: R58.2 122.43,87.68 U$188.4
N$117
  Top 0.61: 135.25,46.99 135.25,44.45 134.89,44.08 LM386M-1.6 129.17,44.08 128.59,43.5 128.59,41.94 C126.+ | 135.25,46.99 135.25,49.2 R59.1 | C109.1 135.32,47.06 135.25,46.99
N$118  (1 unrouted)
  Top 0.305: 98.74,69.53 R69.1
N$119
  Top 0.305: C135.+ 34.38,35.65 34.89,36.16 | 34.89,36.16 L25.1 35.13,36.31 36.2,35.24 36.2,33.43 U$40.2 | 34.89,36.16 C87.1
N$120
  Top 0.305: R70.1 U$57.3 94.93,69.53
N$121
  Top 0.305: 111.09,68.77 111.09,68.8 R60.1 | 112.91,68.86 113,68.77 Q7.1
  Top 0.406: R60.1 112.91,68.86 | R61.2 67.56,87.31 106.68,87.31 110.49,83.5 110.49,70.8 110.81,70.48 110.81,69.06 111.09,68.77
N$122
  Top 0.305: 43.5,66.03 C118.2 43.43,66.61 43.81,66.99 46.04,66.99 47.31,68.26 47.31,70.32 U$41.6
N$123
  Top 0.305: Q5.1 50.93,21.57 L1.2
N$124
  Top 0.305: 61.05,84.94 U$199.1 | 61.05,84.94 R63.1 | 61.05,84.94 61.05,83.28 60.96,83.19 R62.2
N$125
  Top 0.305: U$34.1 R71.2
N$126
  Top 0.305: U$57.1 R72.2
N$127
  Top 0.305: C35.1 C52.2 R96.1
N$128
  Top 0.305: U$176.1 120.36,7.83 C120.1 R16.2
N$129
  Top 0.305: C32.1 129.54,11.46 U$162.2
N$130
  Top 0.305: U$1.3 76.03,65.24 76.83,66.04 78.74,66.04 80.33,67.63 C23.1
N$131  (via drill 0.38 pad 0.64)
  Top 0.305: v100.33,35.56 R83.2 | v100.33,37.78 100.33,40.64 99.69,41.27 v94.61,41.27 | v92.71,75.56 92.71,58.42 94.61,56.52 v94.61,49.53 | v92.71,88.58 92.71,89.85 91.12,91.44 v74.3,91.44 | v67.94,91.44 66.04,91.44 65.41,92.08 56.2,92.08 55.88,91.76 53.34,91.76 52.39,90.81 49.53,90.81 46.04,94.3 30.06,94.3 C128.1
  Top 0.406: D13.C 27.72,94.51 C128.1
  Bottom 0.305: v100.33,37.78 v100.33,35.56 | v92.71,88.58 v92.71,75.56 | v67.94,91.44 v74.3,91.44 | v94.61,49.53 v94.61,41.27
N$132
  Top 1.016: J1.3 128.76,85.58 126.36,83.19 126.36,80.03 D14.A D16.A
N$133  (via drill 0.38 pad 0.64)
  Top 0.305: v98.11,27.62 99.06,27.62 99.69,26.99 101.28,26.99 102.55,28.26 R85.1 | v53.98,16.19 53.98,16.51 60.64,23.18 62.55,23.18 67.94,28.57 v67.94,29.53 | v73.66,29.53 v89.22,29.53 | 49.21,16.19 v49.53,16.19 38.1,16.19 37.15,15.24 26.35,15.24 24.45,17.14 9.21,17.14 7.94,15.88 7.94,8.89 9.21,7.62 15.24,7.62 16.51,6.35 LED1.A
  Bottom 0.305: v49.53,16.19 v53.98,16.19 | v67.94,29.53 v73.66,29.53 | v89.22,29.53 96.84,29.53 98.11,28.26 v98.11,27.62
N$134
  Top 0.813: 136.21,80.01 136.21,82.33 J4.1
  Top 1.016: D16.C 136.21,80.01 D15.A
N$135
  Top 0.406: R79.1 16.41,13.97 16.3,14.07 15.24,14.07 | 15.24,14.07 C132.1 | U$163.2 15.24,14.07 | 15.24,14.07
N$136
  Top 0.61: L3.2 12.38,64.41 C133.1
N$137
  Top 0.305: R88.1 25.5,90.59 D12.C D13.A
N$139
  Top 0.305: R90.1 53.24,85.72 45.4,85.72 44.77,86.36 U$143.1
N$140
  Top 0.305: U$204.3 107.88,24.91 R92.1
N$141  (1 unrouted)
  Top 0.61: U$37.GRF U$37.RDS 5.71,47.94 7.62,49.85 8.89,49.85
N$142  (via drill 0.38 pad 0.64)
  Top 0.305: v112.71,29.53 112.71,26.04 111.76,25.08 R92.2 | U$190.2 126.22,28.32 R91.2 | v115.57,29.53 115.57,28.57 115.89,28.26 R91.2 | R91.2 126.36,28.26
  Bottom 0.305: v112.71,29.53 v115.57,29.53
N$143
  Top 0.305: R66.2 130.28,32.49 130.18,32.38 R93.2 128.37,30.7 128.27,30.8 | 128.27,30.8 127.95,30.8 | 128.27,30.8 U$190.3 | 128.27,30.8 128.27,31.43 127.85,31.85 R73.1 127.85,34.08 127.32,34.61 124.14,34.61 | C53.1 123.83,33.34 124.14,33.66 124.14,34.61 | D4.A 123.83,35.24 124.14,34.92 124.14,34.61
N$144
  Top 0.305: R93.1 131.7,29 U$197.1
N$145
  Top 0.305: U$197.2 133.66,29.84 135.57,31.75 R101.1
N$146
  Top 0.305: R95.2 135.04,32.8 R101.2
N$147
  Top 0.305: C134.1 133.99,34.61 R95.1 133.99,34.29
N$148
  Top 0.305: C53.2 R97.1 120.55,31.86 C52.1
N$149
  Top 0.305: 52.07,63.18 52.07,62.87 | 52.07,63.18 R99.1 | C77.1 52.12,63.14 52.07,63.18
N$150
  Top 0.305: R98.2 104.61,22.54 U$204.1
N$152
  Top 0.305: D19.C D10.C | C82.1 50.86,47.1 D19.C | 50.97,45.4 50.97,43.84 Q2.2 50.32,43.33 48.9,41.91 48.9,38.42 48.26,37.78 45.7,37.78 Q3.1 | 50.97,45.4 D19.C | R25.1 51.04,45.47 50.97,45.4
NARROW_A9  (via drill 0.38 pad 0.64)
  Top 0.305: v101.6,56.83 101.6,60.96 100.97,61.59 95.25,61.59 93.98,62.87 R72.1 93.98,64.14
  Bottom 0.305: JS7.8 102.98,32.91 101.6,34.29 v101.6,56.83
POWER_OUT
  Top 0.305: R83.1 100.33,32.38 | 100.33,32.38 R82.2 | 100.33,32.38 101.28,32.38 101.6,32.7 101.6,33.97 101.92,34.29 107.31,34.29 107.58,34.03 JS7.7 107.69,33.02 U$191.P$1
RIT  (via drill 0.38 pad 0.64)
  Top 0.305: JS7.1 107.59,40.51 107.59,41.16 106.52,42.23 88.27,42.23 87.63,41.59 87.63,38.73 86.36,37.47 69.85,37.47 69.22,36.83 69.22,28.89 62.87,22.54 60.96,22.54 54.93,16.51 54.93,15.88 53.34,14.29 v52.39,14.29 | R79.2 16.61,15.88 17.46,15.88 17.78,16.19 21.59,16.19 22.23,15.56 23.18,15.56 C131.1 23.28,15.88 23.81,15.88 25.4,14.29 v41.91,14.29
  Bottom 0.305: v41.91,14.29 v52.39,14.29
S_METER  (via drill 0.38 pad 0.64)
  Top 0.305: JS7.3 108.06,37.99 108.58,37.47 v109.54,37.47 111.44,37.47 112.71,36.2 112.71,31.75 111.44,30.48 v111.44,26.35 | v109.54,41.27 108.9,41.27 106.36,43.81 v96.52,43.81 | v69.53,48.26 v96.52,48.26 | v56.2,48.58 56.52,48.9 56.52,59.05 v56.2,59.37 | v53.02,59.37 R49.1 | 119.17,17.57 119.06,17.46 119.29,17.46 C151.+ | C151.+ 116.93,17.38 116.84,17.46 R84.2 114.52,17.57 U$183.P$1 114.3,19.05 113.35,20 v110.49,20 | D7.C 119.58,17.57 C151.+
  Bottom 0.305: v56.2,48.58 56.52,48.26 v69.53,48.26 | v109.54,41.27 v109.54,37.47 | v111.44,26.35 111.44,24.45 110.49,23.5 v110.49,20 | v96.52,48.26 v96.52,43.81 | v56.2,59.37 v53.02,59.37
SELECT_GREEN
  Top 0.305: U$166.P$2 47.94,13.34 60.33,25.72 62.23,25.72 65.09,28.57 65.09,35.24 63.82,36.51 63.82,49.21 63.5,49.53 61.98,49.53 JS5.2
SELECT_RED
  Top 0.305: U$166.P$6 49.53,4.45 50.16,5.08 50.16,13.65 60.33,23.81 62.23,23.81 66.99,28.57 66.99,35.88 65.72,37.15 65.72,51.75 64.77,52.7 64.77,53.66 63.68,54.75 JS5.6
SELECT_YELLOW
  Top 0.305: U$166.P$4 48.26,6.99 49.21,7.94 49.21,13.65 60.33,24.77 62.23,24.77 66.04,28.57 66.04,35.56 64.77,36.83 64.77,51.12 63.68,52.21 JS5.4
SIDETONE  (via drill 0.38 pad 0.64)  (1 unrouted)
  Top 0.305: v95.89,35.24 v95.89,24.13 | 98.58,22.7 v98.42,22.86 98.74,22.54 R98.1 | v87.95,35.24 71.44,35.24 v70.17,36.51
  Bottom 0.305: 59.28,36.42 59.37,36.51 v70.17,36.51 | v95.89,24.13 97.16,24.13 v98.42,22.86 98.11,23.18 | v87.95,35.24 v95.89,35.24
T  (via drill 0.38 pad 0.64)
  Top 0.305: R15.2 23.83,28.13 26.96,28.13 29.18,30.35 29.18,32.99 29.84,33.66 29.84,37.47 30.8,38.42 30.8,39.37 31.43,40.01 40.96,40.01 v41.27,39.69 | Q7.3 D3.A 116.81,65.62 C110.1 116.96,63.82 116.96,63.71 C145.+ | v105.73,54.61 104.46,54.61 97.16,47.31 v70.8,47.31 | v70.8,42.55 v70.8,45.4 | v70.8,40.64 70.8,40.01 69.85,39.05 v66.67,39.05 | v50.48,40.01 v56.83,40.01 | v43.81,39.69 46.99,39.69 v47.31,40.01
  Top 0.406: 116.84,63.7 116.84,63.82 | 116.84,63.5 C145.+ | v111.76,59.37 112.71,59.37 116.84,63.5 | 116.84,63.5 116.84,63.7 | 116.84,63.7 116.96,63.82
  Bottom 0.305: v47.31,40.01 v50.48,40.01 | v41.27,39.69 v43.81,39.69 | v70.8,45.4 v70.8,47.31 | v70.8,40.64 v70.8,42.55 | v56.83,40.01 57.15,40.01 58.1,39.05 v66.67,39.05
  Bottom 0.406: v105.73,54.61 105.73,59.69 106.36,60.33 110.17,60.33 111.12,59.37 v111.76,59.37
TD  (via drill 0.38 pad 0.64)
  Top 0.305: v24.11,60.33 24.11,57.01 24.73,56.39 v24.73,54.8 | v36.61,56.26 36.58,56.26 36.2,55.88 36.2,55.16 R18.1 | v110.49,44.45 110.49,44.77 110.81,45.09 v110.81,47.62 | v109.54,70.17 109.86,69.85 109.86,65.09 110.49,64.45 110.49,52.07 110.81,51.75 v110.81,50.48 | v112.08,70.17 112.08,71.44 114.11,71.44 114.3,71.62 | v24.73,52.58 24.89,52.58 25.08,52.39 25.08,51.26 R33.2 | 113.98,73.03 113.98,72.39 | v110.81,38.42 111.76,38.42 113.67,36.51 113.67,24.13 v111.76,22.23 | v111.76,17.78 111.76,15.56 116.52,10.79 118.21,10.79 R16.1
  Top 0.406: v28.57,60.33 36.51,60.33 | 36.51,60.33 36.51,60.23 v36.61,60.13 | 112.08,71.44 111.67,71.85 111.67,81.38 v111.44,81.6 | v109.22,81.6 108.27,82.55 67.63,82.55 61.91,76.83 61.91,75.56 59.69,73.34 v44.45,73.34 | v24.11,60.33 R41.1 | v40.96,72.71 36.51,68.26 36.51,60.33
  Top 0.61: C111.1 D3.C 114.3,71.62 114.18,71.62 114.18,73.15 113.98,73.34 113.67,73.34 113.98,73.03 C142.+
  Bottom 0.305: v24.73,52.58 v24.73,54.8 | v111.76,22.23 v111.76,17.78 | v110.81,38.42 110.81,44.13 v110.49,44.45 | v112.08,70.17 v109.54,70.17 | v110.81,50.48 v110.81,47.62
  Bottom 0.406: v36.61,60.13 v36.61,56.26 | v24.11,60.33 v28.57,60.33 | v109.22,81.6 v111.44,81.6 | v44.45,73.34 41.59,73.34 v40.96,72.71
TX_IN_DAH  (via drill 0.38 pad 0.64)
  Top 0.305: JS6.16 61.82,47.37 61.44,47.75 58.9,47.75 57.88,48.77 57.88,68.8 v56.83,69.85 | R76.2 R89.2 58.74,88.69 58.74,86.36 58.74,82.87 58.74,78.42 56.83,76.52 v56.83,74.61
  Bottom 0.305: v56.83,69.85 v56.83,74.61
TX_IN_DIT  (via drill 0.38 pad 0.64)
  Top 0.305: JS6.14 60.64,44.2 60.64,46.35 60.01,46.99 58.74,46.99 58.13,47.59 57.78,47.94 57.15,48.58 57.15,68.26 v55.56,69.85 | v57.15,90.81 R77.2 | v57.15,87.31 57.15,85.41 57.78,84.77 57.78,83.61 R90.2 57.78,83.5 57.78,78.74 55.56,76.52 v55.56,74.3
  Bottom 0.305: v55.56,69.85 v55.56,74.3 | v57.15,87.31 v57.15,90.81
TX_OUT  (via drill 0.38 pad 0.64)
  Top 0.305: v60.64,66.04 60.64,70.48 65.41,75.25 v65.41,76.2 | v65.41,81.6 U$177.P$1 60.96,81.6 R62.1
  Bottom 0.305: JS5.10 60.82,59.83 60.64,60.01 v60.64,66.04 | v65.41,76.2 v65.41,81.6

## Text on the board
tPlace: P/N 78413 | S/A 82112 | JP4, JUMP RC4, 10 | + | JP8, JUMP RG2 | + | JP6, JUMP RG3 | ChipKit | Nar | Med | Uno32 | Here | CW_Speed | Bias | Bias Mon | Function | Select
bPlace: Open 20M | P/N 78413 | Antenna | Key/Paddle | S/A 82112 | Headphone | 20M | + | + | 40M | Battery | 20M | TX_Out | 40M | Ref | Rebel 40/20 Shield | Model 506 | Ten-Tec Inc. @ 2013 | 41, A | 40, G | <Filter | 39, 13 | 20M | 28, 12 | 20M | 37, 11 | RESET | 40M | 40M | Copyright TEN-TEC 2013 | Licensed under OHL: | 3V3 | 36, 10 | http://www.tapr.org/OHL | 5V0 | 35, 9 | GND | 34, 8 | GND | 33, 7 | VIN | Code-Read | DDS> | 32, 6 | 31, 5 | A0, A6 | <Filter | 30, 4 | A1, A7 | 29, 3 | A2, A8 | 28, 2 | A3, A9 | 27, 1 | [A4], A10 | RF-Power | Side-Tone | 26, 0 | [A5], A11 | BFO | Switch | AGC | RIT | VOL | Led | Function | Select
Document: NOTES FOR TEN-TEC P/N 78413 | 1. DIMENSIONS ARE IN INCHES. | 2. MATERIAL IS STANDARD GRADE FR4. | 5.70 | 35420 | Finish is to be HASL (hot Ait Solder Level) | 35252 | 35252 | 35266 | FINISHED PCB THICKNESS INCLUDING ALL COATINGS AND PADS TO BE 0.062 +0.005/-0.003. | 3. USE THE FOLLOWING TO FABRICATE THE PC BOARD. | ARTWORK | Assembly layer Assm.gbr | Component side silk Topsilk.gbr | Component copper Top.gbr | Solder copper Bottom.gbr | SOLDERMASK | SOLDER MASK TOP Smt.gbr | 3.7750 | SOLDER MASK BOTTOM Smb.gbr | DRILL FILE | Drill info | Drill.ncd | 4. BOARD OUTLINE DIMENSION TOLERANCE IS +/- 0.005. | Notch | 0.7 | 32156 | 32156 | 32122 | 38348 | 38348 | 28192 | 28192 | 30907 | 30907 | RIT | Volume | 2.3375 | 1.025 | 2.3375
tDocu: +8.0V | Rebel Model 506 | Ten-Tec Inc @2013 | Encoder
bDocu: ANT | KEY/PADDLE | Headphone/SPK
